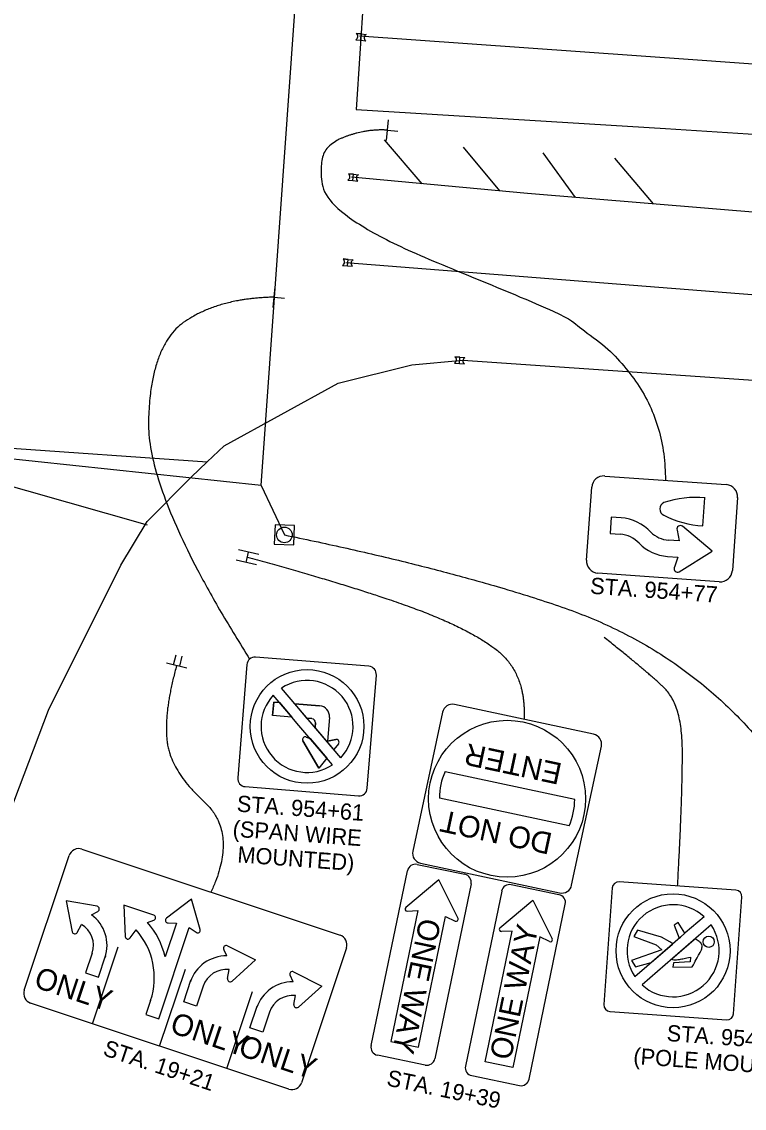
# Model space of a CAD drawing. Extents: x 1847379 to 1850904, y 217032 to 220169.
# Drawn here: x 1849556.2 to 1849667.4, y 218651.7 to 218819 of the extents above; entities that cross this region are included whole.
import ezdxf

# ---------------------------------------------------------------- set-up
doc = ezdxf.new("R2010")
doc.units = 0
for name, color, linetype in [('BR_P_Gen_Approach_Slab_Hidden', 7, 'Continuous'), ('BR_P_Gen_Phase_Construction', 7, 'Continuous'), ('PM_P_Cells', 7, 'Continuous'), ('PM_P_CL_Double_Solid', 7, 'Continuous'), ('PM_P_Edge_Line', 7, 'Continuous'), ('PM_P_Lane_Line', 7, 'Continuous'), ('PM_P_Stop_Line', 7, 'Continuous'), ('PM_P_Transverse_Line', 7, 'Continuous'), ('PM_X_Stop_Line', 7, 'Continuous'), ('SG_X_Wiring', 7, 'Continuous'), ('SN_X_Foundation', 7, 'Continuous'), ('SN_X_Public', 7, 'Continuous'), ('SN_X_Text', 7, 'Continuous')]:
    doc.layers.add(name, color=color, linetype=linetype)

msp = doc.modelspace()

# ---------------------------------------------------------------- linework, layer by layer
at = {"layer": 'BR_P_Gen_Approach_Slab_Hidden'}
for p, q in [((1849582.25, 218748.91), (1849584.7, 218751.23)), ((1849575.49, 218742.06), (1849582.25, 218748.91)), ((1849571.45, 218735.34), (1849575.49, 218742.06)), ((1849560.29, 218713.02), (1849571.45, 218735.34)), ((1849553.54, 218695.13), (1849560.29, 218713.02))]:
    msp.add_line(p, q, dxfattribs=at)
at = {"layer": 'BR_P_Gen_Phase_Construction'}
msp.add_line((1849518.03, 218755.98), (1849584.7, 218751.23), dxfattribs=at)
at = {"layer": 'PM_P_Cells'}
for p, q in [((1849608.43, 218817.14), (1849607.66, 218817.21)), ((1849607.66, 218817.21), (1849608.43, 218817.14)), ((1849607.57, 218816.24), (1849608.34, 218816.17)), ((1849607.57, 218816.24), (1849608.34, 218816.17)), ((1849608.34, 218816.17), (1849608.43, 218817.14)), ((1849608.34, 218816.17), (1849609.11, 218816.1)), ((1849608.43, 218817.14), (1849609.19, 218817.07)), ((1849607.21, 218795.53), (1849606.44, 218795.6)), ((1849606.44, 218795.6), (1849607.21, 218795.53)), ((1849607.12, 218794.56), (1849607.21, 218795.53)), ((1849607.21, 218795.53), (1849607.98, 218795.47)), ((1849606.36, 218794.63), (1849607.12, 218794.56)), ((1849606.36, 218794.63), (1849607.12, 218794.56)), ((1849607.12, 218794.56), (1849607.89, 218794.49)), ((1849606.41, 218782.42), (1849605.64, 218782.49)), ((1849605.64, 218782.49), (1849606.41, 218782.42)), ((1849606.32, 218781.45), (1849606.41, 218782.42)), ((1849606.41, 218782.42), (1849607.17, 218782.35)), ((1849605.55, 218781.51), (1849606.32, 218781.45)), ((1849605.55, 218781.51), (1849606.32, 218781.45)), ((1849606.32, 218781.45), (1849607.09, 218781.38)), ((1849623.61, 218767.37), (1849622.84, 218767.44)), ((1849622.84, 218767.44), (1849623.61, 218767.37)), ((1849623.52, 218766.39), (1849623.61, 218767.37)), ((1849623.61, 218767.37), (1849624.38, 218767.3)), ((1849622.75, 218766.46), (1849623.52, 218766.39)), ((1849622.75, 218766.46), (1849623.52, 218766.39)), ((1849623.52, 218766.39), (1849624.29, 218766.32))]:
    msp.add_line(p, q, dxfattribs=at)
for centre, start, end in [((1849607.31, 218816.75), 296.8063, 52.8586), ((1849607.31, 218816.75), 296.8063, 52.8586), ((1849609.45, 218816.56), 116.8063, 232.8586), ((1849606.1, 218795.15), 296.8063, 52.8586), ((1849606.1, 218795.15), 296.8063, 52.8586), ((1849608.24, 218794.95), 116.8063, 232.8586), ((1849605.29, 218782.03), 296.8063, 52.8586), ((1849605.29, 218782.03), 296.8063, 52.8586), ((1849607.43, 218781.83), 116.8063, 232.8586), ((1849622.49, 218766.98), 296.8063, 52.8586), ((1849622.49, 218766.98), 296.8063, 52.8586), ((1849624.64, 218766.78), 116.8063, 232.8586)]:
    msp.add_arc(centre, 0.576, start, end, dxfattribs=at)
at = {"layer": 'PM_P_CL_Double_Solid'}
for p, q in [((1849634.02, 218792.58), (1849606.94, 218795.07)), ((1849683.32, 218788.47), (1849634.02, 218792.58))]:
    msp.add_line(p, q, dxfattribs=at)
at = {"layer": 'PM_P_Edge_Line'}
for p, q in [((1849607.64, 218805.52), (1849655.22, 218802.6)), ((1849655.22, 218802.6), (1849705.27, 218799.28)), ((1849604.89, 218763.36), (1849616.18, 218766.17)), ((1849616.18, 218766.17), (1849624.07, 218766.93)), ((1849587.31, 218753.7), (1849604.89, 218763.36)), ((1849584.7, 218751.23), (1849587.31, 218753.7))]:
    msp.add_line(p, q, dxfattribs=at)
msp.add_lwpolyline([(1849624.07, 218766.93), (1849675.44, 218763.35), (1849725.59, 218759.36), (1849777.06, 218755.28), (1849832.17, 218750.77)], dxfattribs=at)
at = {"layer": 'PM_P_Lane_Line'}
msp.add_line((1849606.07, 218781.96), (1849881.96, 218760.04), dxfattribs=at)
msp.add_lwpolyline([(1849608.14, 218816.84), (1849659.46, 218813.21), (1849709.31, 218809.62), (1849760.21, 218805.9), (1849807.22, 218802.44), (1849857.63, 218799.12), (1849906.82, 218795.7), (1849957.46, 218791.82), (1850014.55, 218787.19), (1850067.13, 218782.71), (1850118.03, 218778.2), (1850167.47, 218773.95), (1850186.14, 218772.34)], dxfattribs=at)
at = {"layer": 'PM_P_Stop_Line'}
msp.add_line((1849610.73, 218851.87), (1849607.64, 218805.52), dxfattribs=at)
at = {"layer": 'PM_P_Transverse_Line'}
for p, q in [((1849611.95, 218800.81), (1849617.75, 218794.08)), ((1849624.12, 218799.72), (1849629.67, 218792.98)), ((1849636.38, 218798.83), (1849641.36, 218791.97)), ((1849647.4, 218798.01), (1849653.36, 218790.97))]:
    msp.add_line(p, q, dxfattribs=at)
at = {"layer": 'PM_X_Stop_Line'}
msp.add_lwpolyline([(1849575.51, 218741.51), (1849544.66, 218750.3), (1849518.15, 218757.47)], dxfattribs=at)
at = {"layer": 'SG_X_Wiring'}
for q in [(1849599.9, 218844.52), (1849488.92, 218758.66), (1849596.59, 218740)]:
    msp.add_line((1849593, 218747.62), q, dxfattribs=at)
at = {"layer": 'SN_X_Foundation'}
msp.add_lwpolyline([(1849598.04, 218738.45), (1849598.15, 218741.45), (1849595.15, 218741.55), (1849595.04, 218738.56)], close=True, dxfattribs=at)
msp.add_circle((1849596.59, 218740), 1.2, dxfattribs=at)
at = {"layer": 'SN_X_Public'}
for p, q in [((1849612.3, 218800.74), (1849612.6, 218803.92)), ((1849612.45, 218802.33), (1849614.04, 218802.18)), ((1849594.89, 218775.01), (1849595.19, 218778.2)), ((1849595.04, 218776.61), (1849596.63, 218776.46)), ((1849661.01, 218741.4), (1849661.31, 218745.73)), ((1849646.89, 218742.76), (1849646.71, 218740.22)), ((1849648.4, 218742.65), (1849646.89, 218742.76)), ((1849646.71, 218740.22), (1849648.27, 218740.11)), ((1849657.01, 218740.75), (1849657.34, 218739.07)), ((1849662.41, 218737.49), (1849657.85, 218741.34)), ((1849661.01, 218741.4), (1849661.01, 218741.4)), ((1849657.34, 218739.07), (1849655.72, 218739.19)), ((1849592.65, 218736.98), (1849589.53, 218737.69)), ((1849590.73, 218735.78), (1849591.09, 218737.34)), ((1849657.34, 218734.32), (1849662.41, 218737.49)), ((1849592.29, 218735.42), (1849589.17, 218736.13)), ((1849590.91, 218736.56), (1849590.91, 218736.56)), ((1849655.54, 218736.7), (1849657.15, 218736.58)), ((1849657.15, 218736.58), (1849656.6, 218735.02)), ((1849581.57, 218719.51), (1849578.46, 218720.27)), ((1849579.54, 218720), (1849579.92, 218721.56)), ((1849580.48, 218719.77), (1849580.86, 218721.33)), ((1849580.01, 218719.89), (1849580.01, 218719.89)), ((1849605.28, 218705.7), (1849596.15, 218716.41)), ((1849594.95, 218714.27), (1849594.78, 218712.19)), ((1849594.78, 218712.19), (1849594.95, 218714.27)), ((1849595.85, 218714.19), (1849594.95, 218714.27)), ((1849594.95, 218714.27), (1849595.85, 218714.19)), ((1849595.85, 218714.19), (1849596.98, 218712.86)), ((1849602.01, 218713.7), (1849598.2, 218714.01)), ((1849598.25, 218713.94), (1849598.2, 218714.01)), ((1849598.2, 218714.01), (1849602.01, 218713.7)), ((1849600.11, 218711.76), (1849598.25, 218713.94)), ((1849597.76, 218711.95), (1849594.78, 218712.19)), ((1849597.76, 218711.95), (1849594.78, 218712.19)), ((1849596.98, 218712.86), (1849597.76, 218711.95)), ((1849600.83, 218711.71), (1849600.11, 218711.76)), ((1849600.83, 218711.71), (1849600.11, 218711.76)), ((1849603.54, 218711.91), (1849603.24, 218708.23)), ((1849603.54, 218711.91), (1849603.24, 218708.23)), ((1849601.38, 218711.06), (1849601.32, 218710.34)), ((1849601.32, 218710.34), (1849601.38, 218711.06)), ((1849604.19, 218706.96), (1849601.32, 218710.34)), ((1849599.97, 218708.88), (1849600.57, 218708.64)), ((1849599.97, 218708.88), (1849600.57, 218708.64)), ((1849600.57, 218708.65), (1849603.13, 218705.65)), ((1849604.5, 218708.52), (1849603.24, 218708.23)), ((1849603.24, 218708.23), (1849604.5, 218708.52)), ((1849599.45, 218708.29), (1849601.87, 218704.1)), ((1849601.87, 218704.1), (1849599.45, 218708.29)), ((1849604.91, 218707.85), (1849604.19, 218706.96)), ((1849604.91, 218707.85), (1849604.19, 218706.96)), ((1849603.13, 218705.65), (1849601.87, 218704.1)), ((1849603.13, 218705.65), (1849601.87, 218704.1)), ((1849621.32, 218703.56), (1849641.28, 218699.29)), ((1849640.41, 218695.21), (1849620.45, 218699.48)), ((1849620.34, 218686.88), (1849615.27, 218682.63)), ((1849623.31, 218680.96), (1849620.34, 218686.88)), ((1849567.77, 218682.82), (1849563.01, 218683.65)), ((1849563.01, 218683.65), (1849563.94, 218678.91)), ((1849582.31, 218683.91), (1849578.45, 218681)), ((1849583.64, 218679.27), (1849582.31, 218683.91)), ((1849629.77, 218679.48), (1849634.85, 218683.74)), ((1849634.85, 218683.74), (1849637.81, 218677.82)), ((1849566.92, 218681.52), (1849567.9, 218682.04)), ((1849576.48, 218681.46), (1849571.9, 218682.99)), ((1849571.9, 218682.99), (1849572.11, 218678.16)), ((1849617.13, 218682.15), (1849612.96, 218662.02)), ((1849615.48, 218682.07), (1849617.13, 218682.15)), ((1849564.72, 218678.8), (1849565.35, 218680.04)), ((1849575.53, 218680.33), (1849576.49, 218680.68)), ((1849579.98, 218680.23), (1849578.26, 218675.06)), ((1849578.69, 218680.25), (1849579.98, 218680.23)), ((1849617.24, 218661.14), (1849621.41, 218681.26)), ((1849621.41, 218681.26), (1849622.89, 218680.54)), ((1849657.2, 218680.3), (1849656.59, 218679.93)), ((1849657.2, 218680.3), (1849656.59, 218679.93)), ((1849658.24, 218678.68), (1849657.2, 218680.3)), ((1849658.24, 218678.68), (1849657.2, 218680.3)), ((1849572.87, 218677.94), (1849573.76, 218679.19)), ((1849577.27, 218665.49), (1849581.96, 218679.57)), ((1849581.96, 218679.57), (1849583, 218678.81)), ((1849627.47, 218658.88), (1849631.63, 218679.01)), ((1849631.63, 218679.01), (1849629.98, 218678.93)), ((1849650.94, 218679.15), (1849650.36, 218678.16)), ((1849650.94, 218679.15), (1849650.36, 218678.16)), ((1849654.64, 218678.05), (1849650.94, 218679.15)), ((1849654.64, 218678.05), (1849650.94, 218679.15)), ((1849662.27, 218679.94), (1849651.63, 218670.72)), ((1849656.59, 218679.93), (1849657.36, 218677.91)), ((1849656.59, 218679.93), (1849657.36, 218677.91)), ((1849587.83, 218676.74), (1849592.14, 218674.55)), ((1849635.92, 218678.12), (1849631.75, 218657.99)), ((1849637.39, 218677.39), (1849635.92, 218678.12)), ((1849650.36, 218678.16), (1849653.8, 218676.87)), ((1849650.36, 218678.16), (1849653.8, 218676.87)), ((1849653.02, 218674.14), (1849656.31, 218677)), ((1849653.8, 218676.87), (1849654.65, 218676.09)), ((1849653.8, 218676.87), (1849654.65, 218676.09)), ((1849655.89, 218677.36), (1849654.64, 218678.05)), ((1849655.89, 218677.36), (1849654.64, 218678.05)), ((1849656.38, 218677.06), (1849655.89, 218677.36)), ((1849656.38, 218677.06), (1849655.89, 218677.36)), ((1849659.66, 218677.67), (1849656.21, 218674.69)), ((1849656.31, 218677), (1849656.38, 218677.06)), ((1849657.36, 218677.91), (1849657.54, 218678.06)), ((1849659.77, 218677.77), (1849659.66, 218677.67)), ((1849567.02, 218675.62), (1849566, 218672.55)), ((1849567.07, 218664.73), (1849571.02, 218676.59)), ((1849567.98, 218671.89), (1849569.08, 218675.21)), ((1849569.08, 218675.21), (1849569.01, 218674.96)), ((1849587.73, 218675.18), (1849587.26, 218676.19)), ((1849654.65, 218676.09), (1849650.01, 218674.45)), ((1849654.65, 218676.09), (1849650.01, 218674.45)), ((1849659.09, 218675.01), (1849659.01, 218674.29)), ((1849659.09, 218675.01), (1849659.01, 218674.29)), ((1849592.14, 218674.55), (1849588.55, 218671.31)), ((1849650.01, 218674.45), (1849650.62, 218673.51)), ((1849650.01, 218674.45), (1849650.62, 218673.51)), ((1849650.62, 218673.51), (1849653.02, 218674.14)), ((1849650.62, 218673.51), (1849653.02, 218674.14)), ((1849656.45, 218674.1), (1849656.35, 218673.47)), ((1849656.45, 218674.1), (1849656.35, 218673.47)), ((1849656.35, 218673.47), (1849659.35, 218673.48)), ((1849656.35, 218673.47), (1849659.35, 218673.48)), ((1849659.01, 218674.29), (1849656.45, 218674.1)), ((1849659.01, 218674.29), (1849656.45, 218674.1)), ((1849659.35, 218673.48), (1849659.36, 218673.5)), ((1849659.35, 218673.48), (1849659.36, 218673.5)), ((1849566, 218672.55), (1849567.98, 218671.89)), ((1849577.4, 218661.28), (1849581.36, 218673.14)), ((1849587.86, 218671.69), (1849588.1, 218673.07)), ((1849597.92, 218671.18), (1849597.46, 218672.19)), ((1849598.02, 218672.74), (1849602.33, 218670.54)), ((1849581.1, 218668.12), (1849582.21, 218671.44)), ((1849582.21, 218671.44), (1849582.12, 218671.19)), ((1849584.1, 218670.53), (1849583.08, 218667.46)), ((1849602.33, 218670.54), (1849598.74, 218667.31)), ((1849576.01, 218668.33), (1849575.29, 218666.15)), ((1849587.73, 218657.84), (1849591.68, 218669.7)), ((1849598.05, 218667.69), (1849598.29, 218669.07)), ((1849583.08, 218667.46), (1849581.1, 218668.12)), ((1849591.3, 218664.12), (1849592.41, 218667.44)), ((1849592.41, 218667.44), (1849592.32, 218667.19)), ((1849575.29, 218666.15), (1849577.27, 218665.49)), ((1849594.3, 218666.53), (1849593.28, 218663.46)), ((1849593.28, 218663.46), (1849591.3, 218664.12)), ((1849612.96, 218662.02), (1849617.24, 218661.14)), ((1849631.75, 218657.99), (1849627.47, 218658.88))]:
    msp.add_line(p, q, dxfattribs=at)
for points in [[(1849645.89, 218749.07), (1849664.59, 218747.74)], [(1849643.08, 218736.12), (1849643.88, 218747.34)], [(1849666.33, 218745.74), (1849665.53, 218734.52)], [(1849663.52, 218732.78), (1849644.82, 218734.11)], [(1849609.6, 218719.78), (1849592.16, 218721.18)], [(1849590.81, 218720.03), (1849589.41, 218702.59)], [(1849609.35, 218700.99), (1849610.75, 218718.43)], [(1849596.98, 218712.86), (1849594.88, 218715.33)], [(1849644.18, 218709.32), (1849622.78, 218713.9)], [(1849604.01, 218704.62), (1849598.84, 218710.68), (1849596.98, 218712.86)], [(1849620.93, 218712.69), (1849616.35, 218691.3)], [(1849600.57, 218708.64), (1849600.57, 218708.65)], [(1849640.8, 218686.07), (1849645.38, 218707.46)], [(1849590.56, 218701.24), (1849608, 218699.84)], [(1849556.55, 218669.88), (1849563.46, 218690.63)], [(1849565.44, 218691.62), (1849605.17, 218678.38)], [(1849617.01, 218689.27), (1849624.35, 218687.75)], [(1849617.55, 218689.45), (1849638.94, 218684.87)], [(1849609.95, 218661.37), (1849615.53, 218688.3)], [(1849625.32, 218686.27), (1849619.74, 218659.34)], [(1849630.03, 218685.15), (1849624.46, 218658.22)], [(1849638.85, 218684.6), (1849631.51, 218686.12)], [(1849647.05, 218685.65), (1849645.77, 218667.7)], [(1849666.08, 218685.3), (1849648.12, 218686.58)], [(1849665.72, 218666.28), (1849667, 218684.23)], [(1849634.25, 218656.2), (1849639.82, 218683.13)], [(1849661.17, 218681.22), (1849658.27, 218678.71), (1849657.54, 218678.06), (1849657.54, 218678.06)], [(1849657.54, 218678.06), (1849658.24, 218678.68), (1849658.24, 218678.68)], [(1849657.54, 218678.06), (1849656.31, 218677), (1849652.36, 218673.57), (1849650.53, 218671.98)], [(1849659.66, 218677.67), (1849659.66, 218677.67)], [(1849606.16, 218676.41), (1849599.24, 218655.65)], [(1849597.26, 218654.67), (1849557.54, 218667.91)], [(1849646.7, 218666.63), (1849664.65, 218665.35)], [(1849618.26, 218658.37), (1849610.92, 218659.89)], [(1849625.43, 218656.75), (1849632.77, 218655.23)]]:
    msp.add_lwpolyline(points, dxfattribs=at)
for centre, radius in [((1849600.08, 218710.51), 8.75), ((1849630.86, 218699.38), 12.08), ((1849656.4, 218675.97), 8.77), ((1849661.89, 218677.35), 0.864)]:
    msp.add_circle(centre, radius, dxfattribs=at)
for centre, radius, start, end in [((1849645.76, 218747.2), 1.88, 85.9213, 175.9213), ((1849664.46, 218745.87), 1.88, 355.9213, 85.9213), ((1849660.02, 218729.78), 16, 85.3406, 108.3075), ((1849655.44, 218743.99), 1.08, 114.7384, 244.0754), ((1849647.91, 218735.79), 6.87, 42.5734, 85.9213), ((1849661.89, 218756.82), 15.44, 243.3736, 266.7083), ((1849656.04, 218743.55), 4.37, 225.2968, 265.6928), ((1849657.54, 218740.89), 0.547, 55.8723, 194.4166), ((1849647.96, 218735.75), 4.37, 42.5734, 85.9213), ((1849656.05, 218743.55), 6.87, 224.8032, 265.6928), ((1849644.96, 218735.98), 1.87, 175.9213, 265.9213), ((1849657.1, 218734.81), 0.547, 157.4261, 295.9704), ((1849663.66, 218734.65), 1.88, 265.9213, 355.9213), ((1849592.06, 218719.93), 1.25, 85.4185, 175.4185), ((1849609.5, 218718.53), 1.25, 355.4185, 85.4185), ((1849600.08, 218710.51), 7.08, 317.1749, 123.6622), ((1849600.08, 218710.51), 7.08, 137.1749, 303.6622), ((1849600.08, 218710.51), 7.08, 137.1749, 303.6622), ((1849601.87, 218712.04), 1.67, 355.4185, 85.4185), ((1849601.87, 218712.04), 1.67, 355.4185, 85.4185), ((1849622.46, 218712.37), 1.56, 77.9213, 167.9213), ((1849600.78, 218711.11), 0.6, 355.4185, 85.4185), ((1849600.78, 218711.11), 0.6, 355.4185, 85.4185), ((1849599.81, 218708.5), 0.417, 68.0567, 209.9348), ((1849599.81, 218708.5), 0.417, 68.0567, 209.9348), ((1849604.59, 218708.11), 0.417, 320.9023, 102.7804), ((1849604.59, 218708.11), 0.417, 320.9023, 102.7804), ((1849643.85, 218707.79), 1.56, 347.9213, 77.9213), ((1849630.86, 218699.38), 10.42, 156.3844, 179.4583), ((1849590.66, 218702.49), 1.25, 175.4185, 265.4185), ((1849608.1, 218701.09), 1.25, 265.4185, 355.4185), ((1849630.86, 218699.38), 10.42, 336.3844, 359.4583), ((1849564.95, 218690.14), 1.56, 71.568, 161.568), ((1849617.88, 218690.98), 1.56, 167.9213, 257.9213), ((1849616.76, 218688.05), 1.25, 78.2867, 168.2867), ((1849624.1, 218686.52), 1.25, 348.2867, 78.2867), ((1849631.25, 218684.9), 1.25, 78.3095, 168.3095), ((1849639.27, 218686.4), 1.56, 257.9213, 347.9213), ((1849648.05, 218685.58), 1, 85.9213, 175.9213), ((1849666, 218684.3), 1, 355.9213, 85.9213), ((1849638.6, 218683.38), 1.25, 348.3095, 78.3095), ((1849567.7, 218682.41), 0.417, 298.2297, 80.1078), ((1849615.47, 218682.39), 0.314, 129.9142, 272.5299), ((1849656.4, 218675.97), 7.09, 47.7693, 214.1693), ((1849656.4, 218675.97), 7.09, 47.7693, 214.1693), ((1849563.47, 218676.8), 3.75, 341.568, 59.7913), ((1849563.47, 218676.8), 5.84, 341.568, 53.8), ((1849565.54, 218671.82), 13.13, 14.2931, 40.4357), ((1849576.35, 218681.07), 0.417, 289.7297, 71.6078), ((1849578.7, 218680.67), 0.417, 127.0517, 268.9299), ((1849623.03, 218680.82), 0.314, 244.0693, 26.6287), ((1849564.35, 218678.99), 0.417, 191.0752, 332.9534), ((1849565.54, 218671.82), 11.04, 341.568, 41.8597), ((1849583.24, 218679.15), 0.417, 234.2062, 16.0843), ((1849604.67, 218676.9), 1.56, 341.568, 71.568), ((1849629.97, 218679.24), 0.314, 129.9675, 272.5269), ((1849656.4, 218675.97), 7.09, 227.7404, 34.0927), ((1849572.53, 218678.18), 0.417, 182.5752, 324.4534), ((1849587.64, 218676.37), 0.417, 63.0282, 204.9064), ((1849637.53, 218677.68), 0.314, 244.0663, 26.682), ((1849587.66, 218669.34), 5.84, 89.336, 161.568), ((1849587.66, 218669.34), 3.75, 83.3448, 161.568), ((1849588.27, 218671.62), 0.417, 170.1827, 312.0608), ((1849597.83, 218672.37), 0.417, 63.0282, 204.9064), ((1849597.86, 218665.34), 5.84, 89.336, 161.568), ((1849558.03, 218669.39), 1.56, 161.568, 251.568), ((1849597.86, 218665.34), 3.75, 83.3448, 161.568), ((1849598.46, 218667.62), 0.417, 170.1827, 312.0608), ((1849646.77, 218667.63), 1, 175.9213, 265.9213), ((1849664.72, 218666.35), 1, 265.9213, 355.9213), ((1849611.17, 218661.12), 1.25, 168.2867, 258.2867), ((1849618.52, 218659.6), 1.25, 258.2867, 348.2867), ((1849625.68, 218657.97), 1.25, 168.3095, 258.3095), ((1849597.76, 218656.15), 1.56, 251.568, 341.568), ((1849633.03, 218656.45), 1.25, 258.3095, 348.3095)]:
    msp.add_arc(centre, radius, start, end, dxfattribs=at)
for points in [[(1849659.36, 218673.5), (1849659.81, 218674.35), (1849660.54, 218675.7), (1849660.81, 218676.18), (1849660.85, 218676.35), (1849660.86, 218676.52), (1849660.89, 218676.92), (1849660.45, 218677.46), (1849660.03, 218677.65), (1849659.77, 218677.77)], [(1849659.36, 218673.5), (1849659.81, 218674.35), (1849660.54, 218675.7), (1849660.81, 218676.18), (1849660.85, 218676.35), (1849660.86, 218676.52), (1849660.89, 218676.92), (1849660.45, 218677.46), (1849660.03, 218677.65), (1849659.77, 218677.77)], [(1849656.21, 218674.69), (1849656.28, 218674.65), (1849656.48, 218674.57), (1849656.94, 218674.58), (1849657.36, 218674.63), (1849658.1, 218674.78), (1849658.61, 218674.89), (1849659.09, 218675.01)], [(1849656.21, 218674.69), (1849656.28, 218674.65), (1849656.48, 218674.57), (1849656.94, 218674.58), (1849657.36, 218674.63), (1849658.1, 218674.78), (1849658.61, 218674.89), (1849659.09, 218675.01)]]:
    msp.add_open_spline(points, degree=3, dxfattribs=at)
at = {"layer": 'SN_X_Text'}
for points in [[(1849612.45, 218802.33), (1849608.48, 218802.55), (1849601.17, 218799.08), (1849604.12, 218787.55), (1849655.25, 218768.71), (1849655.24, 218748.41)], [(1849595.04, 218776.61), (1849586.4, 218776.43), (1849575.94, 218769.13), (1849575.42, 218745.89), (1849591.25, 218720.88)], [(1849596.59, 218740), (1849622.52, 218734.68), (1849656.27, 218723.03), (1849679.46, 218697.82), (1849679.04, 218684.38)], [(1849590.91, 218736.56), (1849605.6, 218732.59), (1849624.73, 218725.81), (1849633.79, 218718.75), (1849633.48, 218711.61)], [(1849657.1, 218685.94), (1849657.88, 218699.91), (1849657.79, 218713.86), (1849652.19, 218719.15), (1849645.79, 218724.23)], [(1849580.01, 218719.89), (1849577.99, 218712.64), (1849579.11, 218703.63), (1849589.49, 218694.08), (1849585.3, 218685)]]:
    msp.add_open_spline(points, degree=2, dxfattribs=at)

# ---------------------------------------------------------------- texts
at = {"layer": 'SN_X_Public'}
for s, rotation, p in [('ENTER', 167.9213, (1849639.5, 218704.78)), ('DO NOT', 167.9213, (1849638.01, 218694.02)), ('ONE WAY', 258.2867, (1849617.45, 218681.15)), ('ONE WAY', 78.3095, (1849631.43, 218659)), ('ONLY', 341.568, (1849557.87, 218670.43)), ('ONLY', 341.568, (1849578.8, 218663.45)), ('ONLY', 341.568, (1849589.32, 218659.95))]:
    msp.add_text(s, height=3.333, rotation=rotation, dxfattribs=at).set_placement(p)
at = {"layer": 'SN_X_Text'}
for s, rotation, p in [('STA. 954+77', 355.9213, (1849643.59, 218730.96)), ('STA. 954+61', 355.7486, (1849589.21, 218697.41)), ('(SPAN WIRE ', 355.7486, (1849588.57, 218693.55)), ('MOUNTED)', 355.7486, (1849589.3, 218689.59)), ('STA. 954+67', 355.9213, (1849655.36, 218662.08)), ('STA. 19+21', 341.568, (1849568.52, 218659.94)), ('(POLE MOUNTED)', 355.9213, (1849650.23, 218658.54)), ('STA. 19+39', 348.2867, (1849612.2, 218655.24))]:
    msp.add_text(s, height=2.5, rotation=rotation, dxfattribs=at).set_placement(p)

doc.saveas('drawing.dxf')
